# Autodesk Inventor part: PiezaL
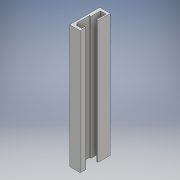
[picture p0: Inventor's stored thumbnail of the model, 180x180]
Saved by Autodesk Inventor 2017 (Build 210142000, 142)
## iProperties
Part Number: PiezaL
Material: Genérico
Document SubType Name: Modeling
Designer: Jaime
Density: 1 g/cm^3
Appearance: Valor por defecto
Author: Jaime
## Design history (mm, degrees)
sketch "Boceto1"
  geometry: L1 (5, 40)-(13.4, 40); L2 (13.4, 4)-(5, 4); L3 (13.4, 26)-(15.4, 26); L4 (15.4, 26)-(15.4, 44); L5 (15.4, 44)-(0, 44); L6 (0, 44)-(0, 0); L7 (0, 0)-(15.4, 0); L8 (15.4, 0)-(15.4, 8); L9 (5, 26)-(3, 26); L10 (3, 26)-(3, 7); L11 (5, 4)-(5, 7); L12 (5, 26)-(5, 40); L13 (13.4, 40)-(13.4, 26); L14 (13.4, 8)-(13.4, 4); L15 (5, 30)-(13.4, 30); L16 (3, 17)-(31.845, 17); L17 (3, 22)-(31.845, 22); L18 (3, 12)-(29.822, 12); L19 (3, 7)-(5, 7); L20 (13.4, 8)-(15.4, 8); 14 further points
  constraints: 40 end point, 13 midpoint, 7 horizontal, 7 perpendicular, 6 parallel, 6 point on line, 6 vertical alignment, 2 horizontal alignment, 1 vertical
  dimensions: "d15" = 8.4 distance of L2.start L2.end; "d19" = 3 distance between parallel lines of L6 L10; "d20" = 2 distance of L9.start L9.end; "d21" = 4 distance between parallel lines of L5 L1; "d22" = 36 distance between parallel lines of L2 L1; "d24" = 4 distance between parallel lines of L7 L2; "d27" = 26 distance between parallel lines of L2 L15; "d29" = 13 distance between parallel lines of L2 L16; "d30" = 5 distance between parallel lines of L17 L16; "d31" = 10 distance between parallel lines of L17 L18; "d32" = 10 distance between parallel lines of L1 L15 (derived); "d34" = 3 distance between parallel lines of L19 L2; "d35" = 8 distance of L7.end L8.end; "d36" = 22 distance from line of L2 point (14.4, 26); "d39" = 18 distance from line of L20 point (14.4, 26) (derived); "d41" = 2 distance between parallel lines of L13 L4
extrude "Extrusión1" new body sketch "Boceto1" distance "d5" = 180; taper "d6" = 0 deg
node "Sólido1"
